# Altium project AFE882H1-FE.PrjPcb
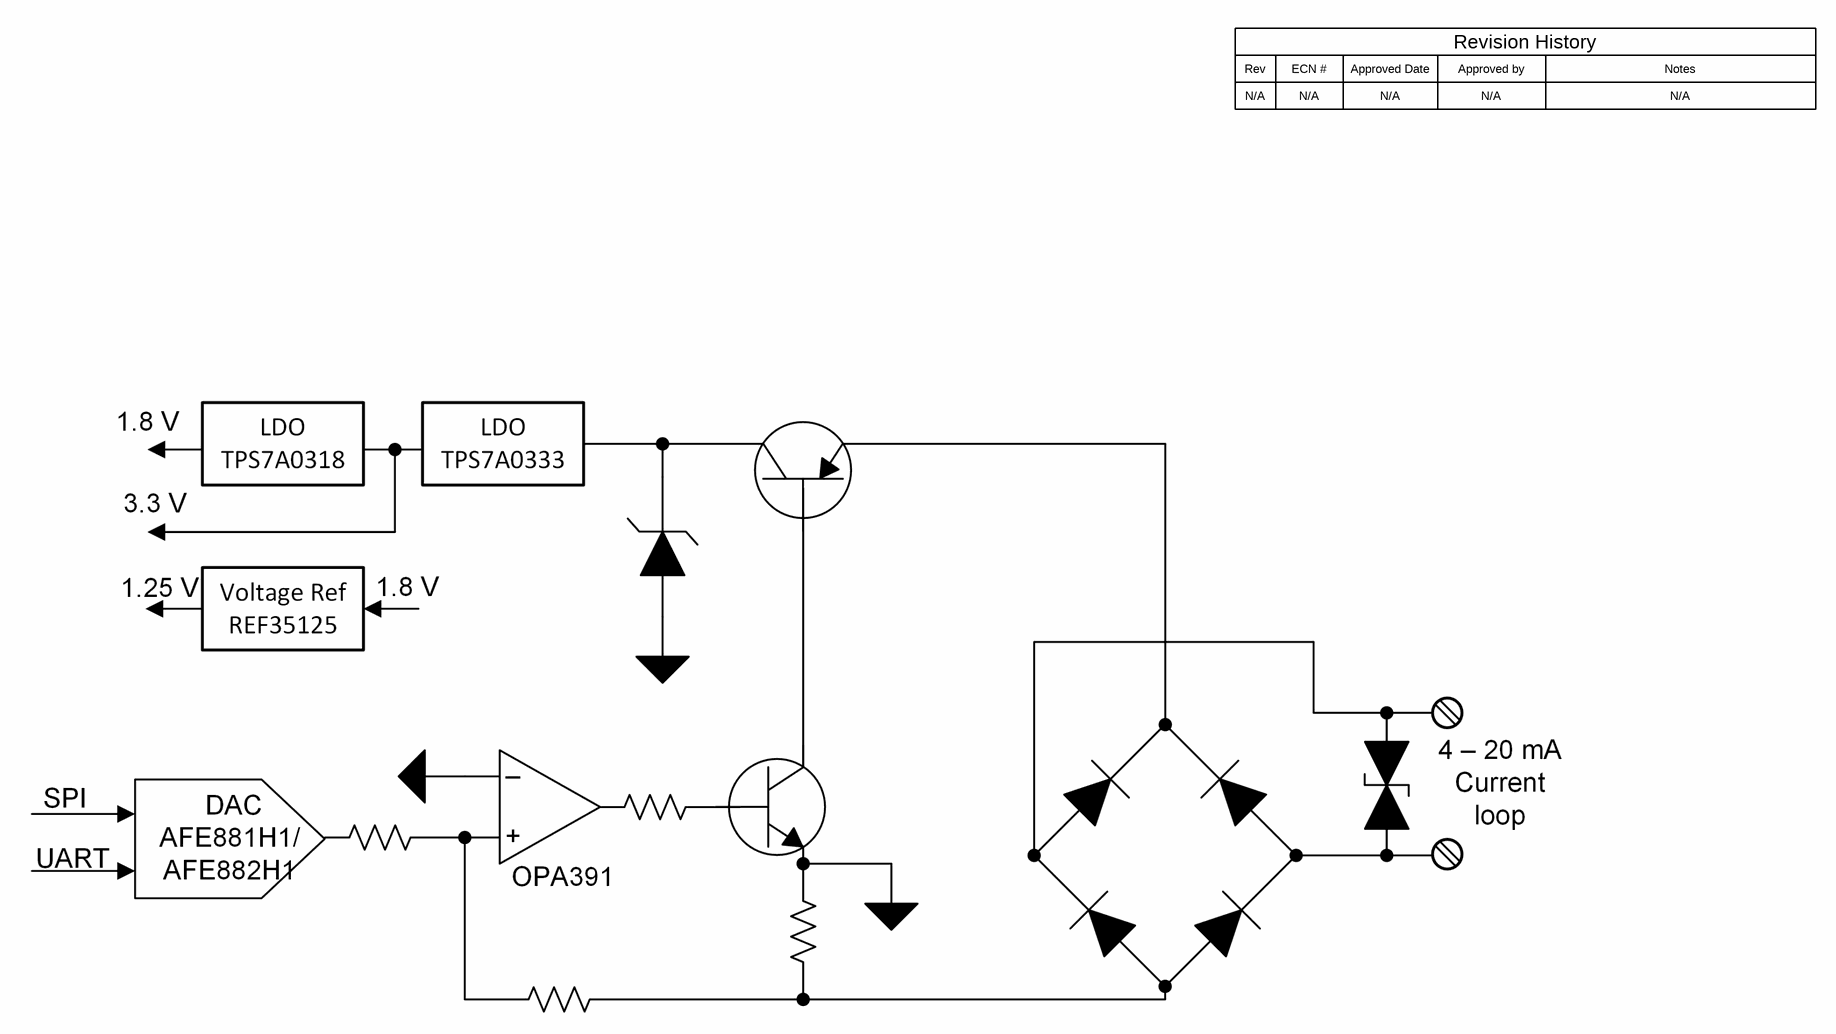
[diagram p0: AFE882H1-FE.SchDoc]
TID: N/A; TechSupport: http://www.ti.com/support; SCH_Rev: E3; PRJ_Title: FT-EVP-AFE; PRJ_Number: TIDA-010982; PRJ_Engineer: A. Noeman; PRJ_Customer: Public Release; PCB_Rev: E3; PCB_Layout: A. Noeman; CopyrightYear: 2024
3 sheets, 102 parts. Net scope: global (net labels, ports and power ports of the same name join across sheets).
Board file: AFE882H1-FE_SG.PcbDoc
Sheets:
  AFE882H1-FE.SchDoc
  AFE882H1-FE_AFE.SchDoc
  AFE882H1-FE_Hardware.SchDoc

## Sheet AFE882H1-FE.SchDoc
size 431 x 279 mm; Date: Not shown in title block; ApprovedBy: Not shown in title block; CheckedBy: Not shown in title block; Author: Not shown in title block; CompanyName: Not shown in title block; Engineer: Not shown in title block; Organization: Not shown in title block; Address1: Not shown in title block; Address2: Not shown in title block; Address3: Not shown in title block; Address4: Not shown in title block; DocumentNumber: 1; Revision: Use project parameter SCH_Rev; SheetNumber: 1; SheetTotal: 3; PageSetup: Record=PageOptions¦CenterHorizontal=True¦CenterVertical=True¦PrintScale=1.00¦XCorrection=1.00¦YCorrection=1.00¦PrintKind=0¦BorderSize=5000000¦LeftOffset=0¦BottomOffset=0¦Orientation=2¦PaperLength=1000¦PaperWidth=1000¦Scale=100¦PaperSource=15¦PrintQuality=600¦MediaType=1¦DitherType=10¦PaperKind=Letter¦PrintScaleMode=1

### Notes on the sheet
- Rev
- N/A
- ECN #
- Approved Date
- Approved by
- Revision History
- Notes

## Sheet AFE882H1-FE_AFE.SchDoc
size 431 x 279 mm; Date: Not shown in title block; ApprovedBy: Not shown in title block; CheckedBy: Not shown in title block; Author: Not shown in title block; CompanyName: Not shown in title block; Engineer: Not shown in title block; Organization: Not shown in title block; Address1: Not shown in title block; Address2: Not shown in title block; Address3: Not shown in title block; Address4: Not shown in title block; DocumentNumber: 2; Revision: Use project parameter SCH_Rev; SheetNumber: 2; SheetTotal: 3; PageSetup: Record=PageOptions¦CenterHorizontal=True¦CenterVertical=True¦PrintScale=1.00¦XCorrection=1.00¦YCorrection=1.00¦PrintKind=0¦BorderSize=5000000¦LeftOffset=0¦BottomOffset=0¦Orientation=2¦PaperLength=1000¦PaperWidth=1000¦Scale=100¦PaperSource=15¦PrintQuality=600¦MediaType=1¦DitherType=10¦PaperKind=Letter¦PrintScaleMode=1
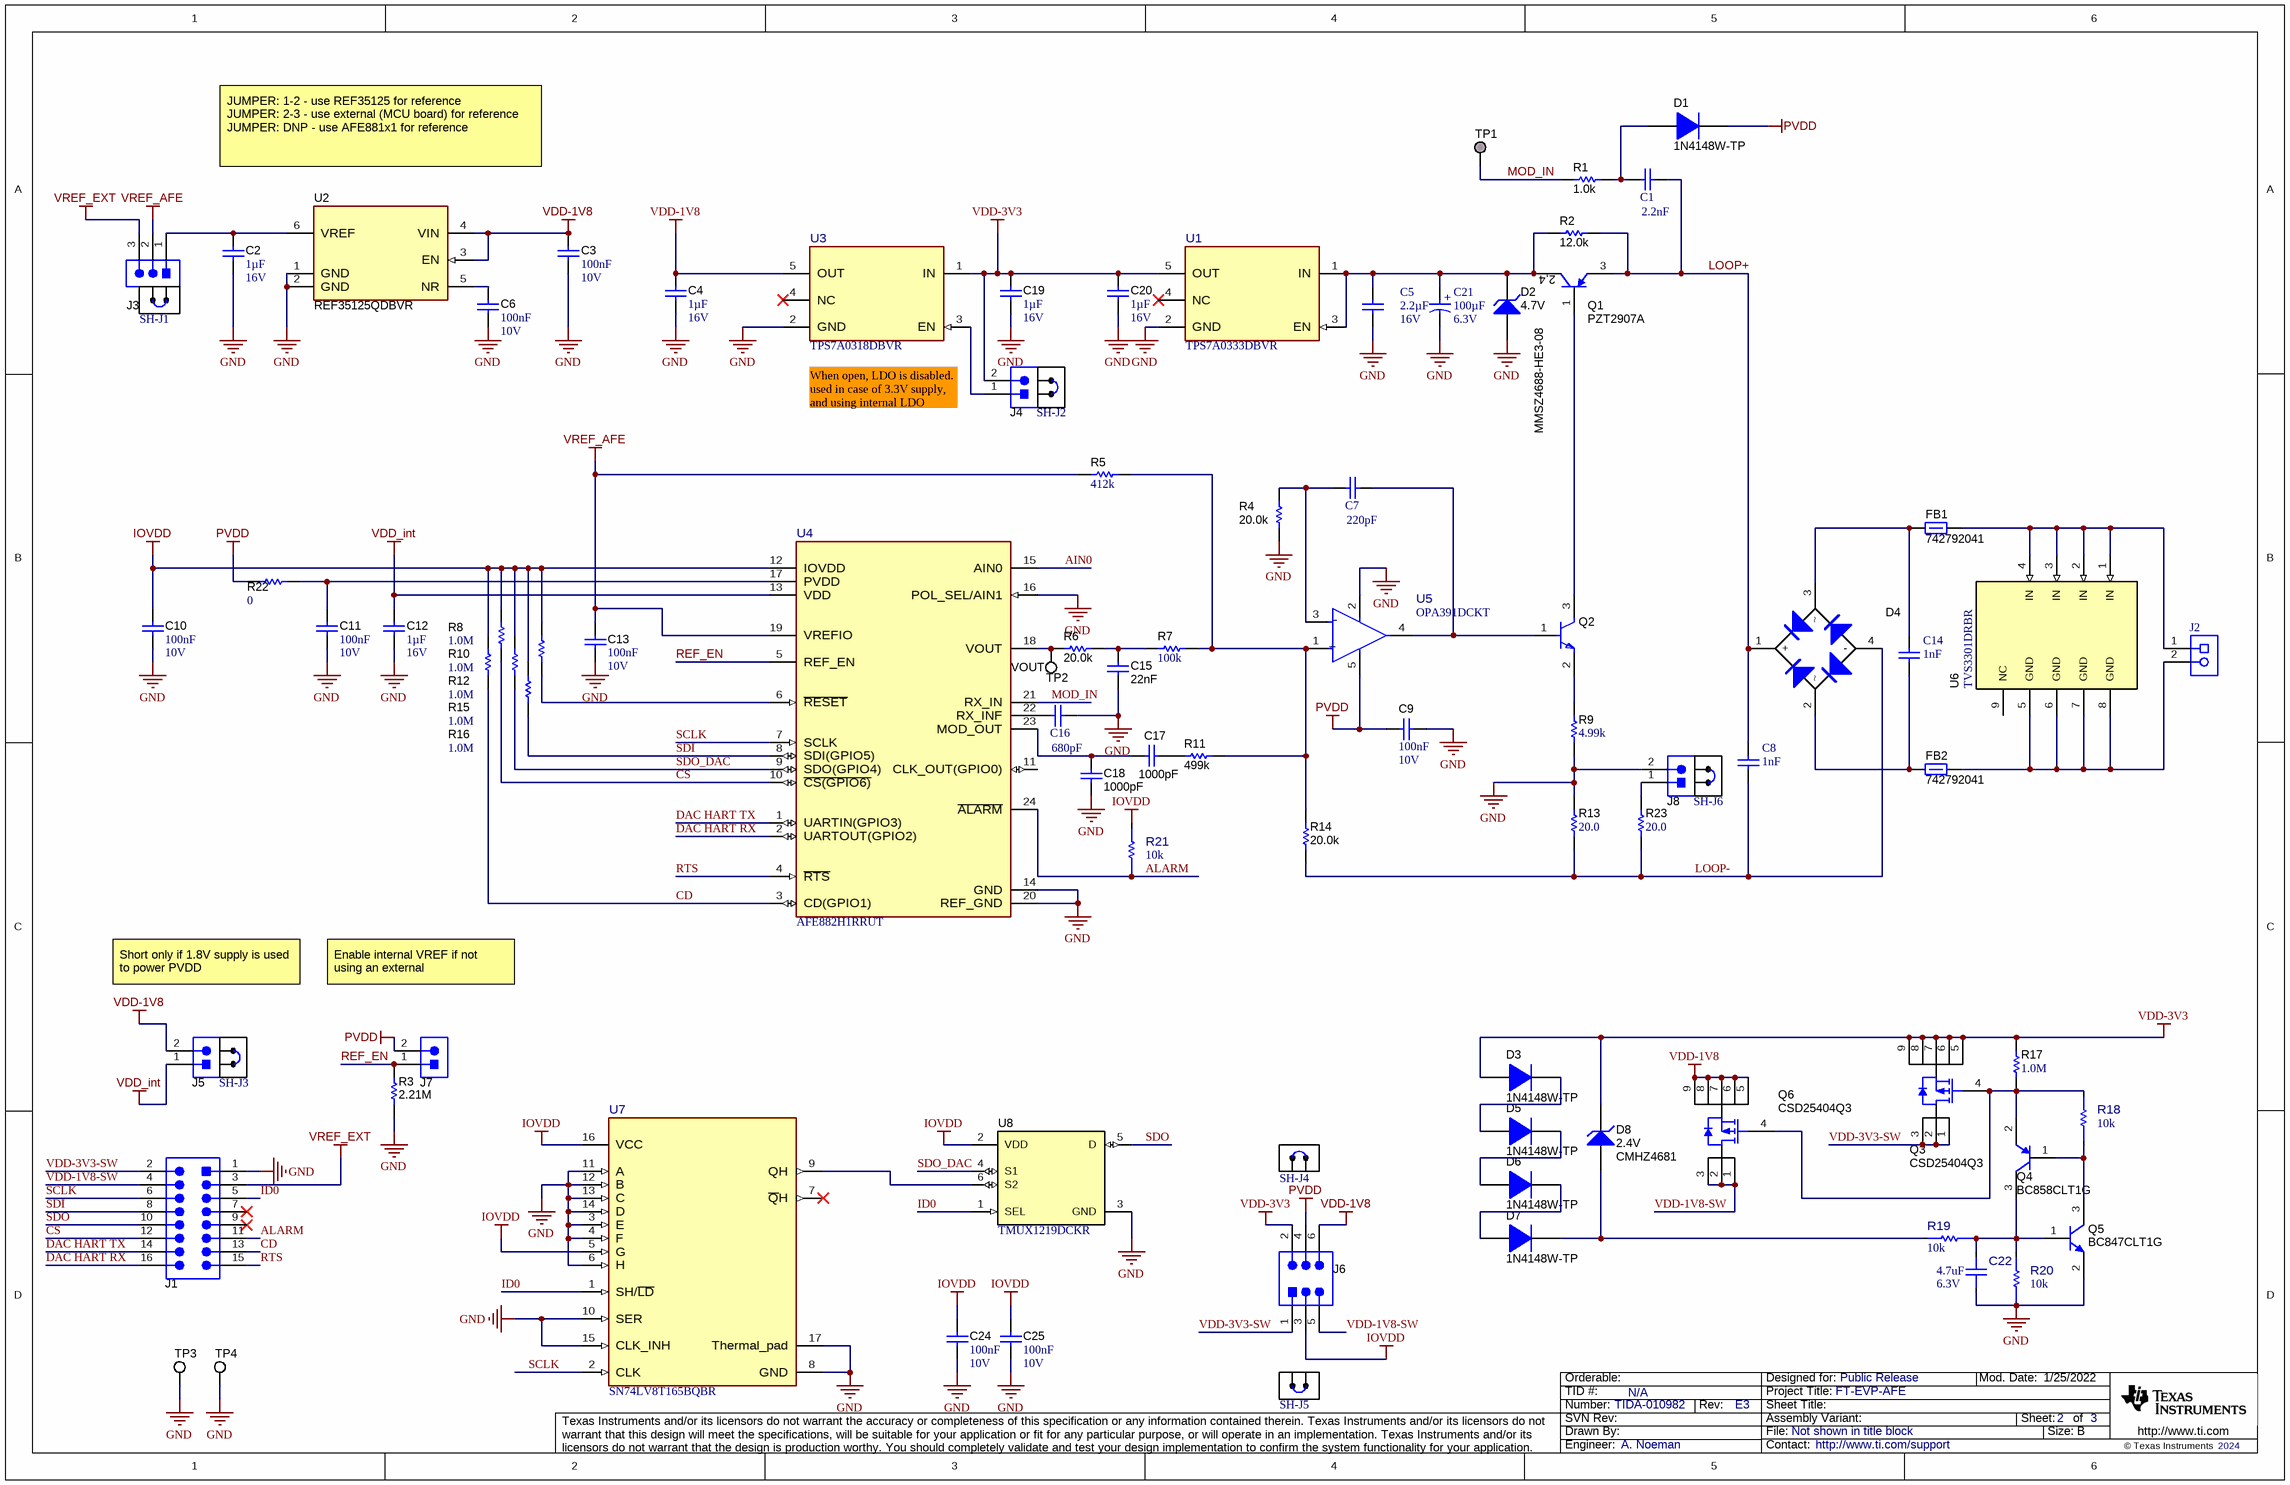
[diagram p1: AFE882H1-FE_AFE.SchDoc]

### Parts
C1  Cap_F: 2.2nF  [WCAP-CSGP_0603_L1.6W0.8H0.8_Reflow]  (hidden comment: 885012006015)
C2  Cap_F: 1µF  VDC_V: 16V  [0603]  (hidden comment: 885012206052)
C3  Cap_F: 100nF  VDC_V: 10V  [0603]  (hidden comment: 885012206020)
C4  Cap_F: 1µF  VDC_V: 16V  [0603]  (hidden comment: 885012206052)
C5  Cap_F: 2.2µF  Rated Voltage (DC): 16V  [WCAP-CSGP_0805_L2W1.25H1.25]  (hidden comment: 885012207052)
C6  Cap_F: 100nF  VDC_V: 10V  [0603]  (hidden comment: 885012206020)
C7  Cap_F: 220pF  [WCAP-CSGP_0603_L1.6W0.8H0.8_Reflow]  (hidden comment: 885012006010)
C8  Cap_F: 1nF  [WCAP-CSGP_0805_L2W1.25H0.8_Reflow]  (hidden comment: 885012207086)
C9  Cap_F: 100nF  VDC_V: 10V  [0603]  (hidden comment: 885012206020)
C10  Cap_F: 100nF  VDC_V: 10V  [0603]  (hidden comment: 885012206020)
C11  Cap_F: 100nF  VDC_V: 10V  [0603]  (hidden comment: 885012206020)
C12  Cap_F: 1µF  VDC_V: 16V  [0603]  (hidden comment: 885012206052)
C13  Cap_F: 100nF  VDC_V: 10V  [0603]  (hidden comment: 885012206020)
C14  Cap_F: 1nF  [WCAP-CSGP_0805_L2W1.25H0.8_Reflow]  (hidden comment: 885012207086)
C15  Cap_F: 22nF  [0603]  (hidden comment: 885012206091)
C16  Cap_F: 680pF  [WCAP-CSGP_0603_L1.6W0.8H0.8_Reflow]  (hidden comment: 885012006013)
C17  ValueDisplayed: 1000pF  [0402]  (hidden comment: 885012205061)
C18  ValueDisplayed: 1000pF  [0402]  (hidden comment: 885012205061)
C19  Cap_F: 1µF  VDC_V: 16V  [0603]  (hidden comment: 885012206052)
C20  Cap_F: 1µF  VDC_V: 16V  [0603]  (hidden comment: 885012206052)
C21  Cap_F: 100µF  Rated Voltage (DC): 6.3V  [WCAP-AS5H_D6.3H5.5]  (hidden comment: 865230143004)
C22  ValueDisplayed: 4.7uF  VDC_V: 6.3V  [FP-885012106005_0603-MFG]  (hidden comment: 885012106005)
C24  Cap_F: 100nF  VDC_V: 10V  [0603]  (hidden comment: 885012206020)
C25  Cap_F: 100nF  VDC_V: 10V  [0603]  (hidden comment: 885012206020)
D1  1N4148W-TP  [SOD-123]
D2  MMSZ4688-HE3-08  value 4.7V  [SOD-123]
D3  1N4148W-TP  [SOD-123]
D4  CD-MBL206SL  [CD-MBL2xxS]  (value not drawn)
D5  1N4148W-TP  [SOD-123]
D6  1N4148W-TP  [SOD-123]
D7  1N4148W-TP  [SOD-123]
D8  CMHZ4681  value 2.4V  [SOD-123]
FB1  742792041  [0805_HV]
FB2  742792041  [0805_HV]
J1  61301621021  [Wurth_61301621021]  (value not drawn)
J2  691214310002  [Wurth_691214310002]  (value not drawn)
J3  61300311121  [WURTH_61300311121]  (value not drawn)
J4  61300211121  [WURTH_61300211121]  (value not drawn)
J5  61300211121  [WURTH_61300211121]  (value not drawn)
J6  61300621121  [Wurth_61300621121]  (value not drawn)
J7  61300211121  [WURTH_61300211121]  (value not drawn)
J8  61300211121  [WURTH_61300211121]  (value not drawn)
Q1  PZT2907A  [SOT-223]
Q2  SMMBT3904LT3G  [FP-SMMBT3904LT3G_SOT23-MFG]  (value not drawn)
Q3  CSD25404Q3  [DQG0008A]
Q4  BC858CLT1G  [SOT-23]
Q5  BC847CLT1G  [SOT-23]
Q6  CSD25404Q3  [DQG0008A]
R1  ValueDisplayed: 1.0k  [0603]  (hidden comment: RC0603JR-071KL)
R2  ValueDisplayed: 12.0k  [0805_HV]  (hidden comment: RG2012P-123-B-T5)
R3  ValueDisplayed: 2.21M  [0603]  (hidden comment: RC0603FR-072M21L)
R4  ValueDisplayed: 20.0k  [0603]  (hidden comment: RG1608P-203-B-T5)
R5  ValueDisplayed: 412k  [0603]  (hidden comment: RT0603BRD07412KL)
R6  ValueDisplayed: 20.0k  [0603]  (hidden comment: RG1608P-203-B-T5)
R7  ValueDisplayed: 100k  [0603]  (hidden comment: RG1608P-104-B-T5)
R8  ValueDisplayed: 1.0M  [0603]  (hidden comment: CRCW06031M00JNEA)
R9  ValueDisplayed: 4.99k  [0603]  (hidden comment: RT0603BRD074K99L)
R10  ValueDisplayed: 1.0M  [0603]  (hidden comment: CRCW06031M00JNEA)
R11  ValueDisplayed: 499k  [0603]  (hidden comment: RT0603DRE07499KL)
R12  ValueDisplayed: 1.0M  [0603]  (hidden comment: CRCW06031M00JNEA)
R13  ValueDisplayed: 20.0  [0805_HV]  (hidden comment: RT0805BRD0720RL)
R14  ValueDisplayed: 20.0k  [0603]  (hidden comment: RG1608P-203-B-T5)
R15  ValueDisplayed: 1.0M  [0603]  (hidden comment: CRCW06031M00JNEA)
R16  ValueDisplayed: 1.0M  [0603]  (hidden comment: CRCW06031M00JNEA)
R17  ValueDisplayed: 1.0M  [0603]  (hidden comment: CRCW06031M00JNEA)
R18  value 10k  [FP-CRCW060310K0FKEAC_0603-MFG]  (hidden comment: CRCW060310K0FKEAC)
R19  value 10k  [FP-CRCW060310K0FKEAC_0603-MFG]  (hidden comment: CRCW060310K0FKEAC)
R20  value 10k  [FP-CRCW060310K0FKEAC_0603-MFG]  (hidden comment: CRCW060310K0FKEAC)
R21  value 10k  [FP-CRCW060310K0FKEAC_0603-MFG]  (hidden comment: CRCW060310K0FKEAC)
R22  ValueDisplayed: 0  [0603]  (hidden comment: RCS06030000Z0EA)
R23  ValueDisplayed: 20.0  [0805_HV]  (hidden comment: RT0805BRD0720RL)
SH-J1  60900213421  [Wurth_60900213421]  (value not drawn)
SH-J2  60900213421  [Wurth_60900213421]  (value not drawn)
SH-J3  60900213421  [Wurth_60900213421]  (value not drawn)
SH-J4  60900213421  [Wurth_60900213421]  (value not drawn)
SH-J5  60900213421  [Wurth_60900213421]  (value not drawn)
SH-J6  60900213421  [Wurth_60900213421]  (value not drawn)
TP1  TP_H0.45P0.75  [TP_H045P075]  (value not drawn)  (no BOM)
TP2  VOUT  [Keystone5002]
TP3  GND  [Keystone5002]  (value not drawn)
TP4  GND  [Keystone5002]  (value not drawn)
U1  TPS7A0333DBVR  [DBV0005A-MFG]
U2  REF35125QDBVR  [DBV0006A-MFG]
U3  TPS7A0318DBVR  [DBV0005A-MFG]
U4  AFE882H1RRUT  [RRU0024A-MFG]
U5  OPA391DCKT  [DCK0005A-MFG]
U6  TVS3301DRBR  [DRB0008A]
U7  SN74LV8T165BQBR  [BQB0016A-MFG]
U8  TMUX1219DCKR  [DCK0006A_N]  (no BOM)

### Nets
GND: C2.2 C3.2 C4.2 C5.1 C6.2 C9.2 C10.2 C11.2 C12.2 C13.2 C15.2 C16.2 C18.1 C19.2 C20.2 C21.2(N) C22.1 C24.2 C25.2 D2.2(A) J1.1 J8.2 Q5.2(E) R3.2 R4.1 R9.1 R13.2 R20.1 TP3.1 TP4.1 U1.2(GND) U2.1(GND) U2.2(GND) U3.2(GND) U4.14(GND) U4.16(POL_SEL/AIN1) U4.20(REF_GND) U5.2(V-) U7.3(E) U7.4(F) U7.6(H) U7.8(GND) U7.10(SER) U7.11(A) U7.12(B) U7.13(C) U7.14(D) U7.15(CLK_INH) U7.17(Thermal_pad) U8.3(GND)
IOVDD: C10.1 C24.1 C25.1 J6.3 R8.2 R10.2 R12.2 R15.2 R16.2 R21.2 U4.12(IOVDD) U7.5(G) U7.16(VCC) U8.2(VDD)
PVDD: C9.1 D1.1(K) J6.4 J7.2 R22.1 U5.5(V+)
VDD-1V8: C3.1 C4.1 J5.2 J6.6 Q6.5(S) Q6.6(S) Q6.7(S) Q6.8(S) Q6.9(S) U2.3(EN) U2.4(VIN) U3.5(OUT)
VDD-3V3: C19.1 C20.1 D3.2(A) D8.1(K) J4.2 J6.2 Q3.5(S) Q3.6(S) Q3.7(S) Q3.8(S) Q3.9(S) R17.2 U1.5(OUT) U3.1(IN)
VDD_int: C12.1 J5.1 U4.13(VDD)
VREF_AFE: C13.1 J3.2 R5.1 U4.19(VREFIO)
VREF_EXT: J1.3 J3.3
AIN0: U4.15(AIN0)
ALARM: J1.11 R21.1 U4.24(~{ALARM})
CD: J1.13 R16.1 U4.3(CD(GPIO1))
CS: J1.12 R15.1 U4.10(~{CS(GPIO6)})
DAC HART RX: J1.16 U4.2(UARTOUT(GPIO2))
DAC HART TX: J1.14 U4.1(UARTIN(GPIO3))
ID0: J1.5 U7.1(SH/~{LD}) U8.1(SEL)
LOOP+: C1.2 C8.2 D4.1(+) Q1.3(E) R2.2
LOOP-: C8.1 D4.4(-) R13.1 R14.1 R23.1
MOD_IN: R1.1 TP1.1 U4.21(RX_IN)
REF_EN: J7.1 R3.1 U4.5(REF_EN)
RTS: J1.15 U4.4(~{RTS})
SCLK: J1.6 U4.7(SCLK) U7.2(CLK)
SDI: J1.8 R10.1 U4.8(SDI(GPIO5))
SDO: J1.10 U8.5(D)
SDO_DAC: R12.1 U4.9(SDO(GPIO4)) U8.4(S1)
VDD-1V8-SW: J1.4 J6.5 Q6.1(D) Q6.2(D) Q6.3(D)
VDD-3V3-SW: J1.2 J6.1 Q3.1(D) Q3.2(D) Q3.3(D)
NetC1_1: C1.1 D1.2(A) R1.2
NetC2_1: C2.1 J3.1 U2.6(VREF)
NetC5_2: C5.2 C21.1(P) D2.1(K) Q1.2(C) Q1.4(C) R2.1 U1.1(IN) U1.3(EN)
NetC6_1: C6.1 U2.5(NR)
NetC7_1: C7.1 R4.2 U5.3(-IN)
NetC7_2: C7.2 Q2.1(BASE) U5.4(OUT)
NetC11_1: C11.1 R22.2 U4.17(PVDD)
NetC14_1: C14.1 D4.2 FB2.1
NetC14_2: C14.2 D4.3 FB1.1
NetC15_1: C15.1 R6.1 R7.1
NetC16_1: C16.1 U4.22(RX_INF)
NetC17_1: C17.1 R11.1
NetC17_2: C17.2 C18.2 U4.23(MOD_OUT)
NetC22_2: C22.2 Q4.3(C) Q5.1(B) R19.1 R20.2
NetD3_1: D3.1(K) D5.2(A)
NetD5_1: D5.1(K) D6.2(A)
NetD6_1: D6.1(K) D7.2(A)
NetD7_1: D7.1(K) D8.2(A) R19.2
NetFB1_2: FB1.2 J2.1 U6.1(IN) U6.2(IN) U6.3(IN) U6.4(IN)
NetFB2_2: FB2.2 J2.2 U6.5(GND) U6.6(GND) U6.7(GND) U6.8(GND)
NetJ4_1: J4.1 U3.3(EN)
NetJ8_1: J8.1 R23.2
NetQ1_1: Q1.1(B) Q2.3(COLLECTOR)
NetQ2_2: Q2.2(EMITTER) R9.2
NetQ3_4: Q3.4(G) Q4.2(E) Q6.4(G) R17.1 R18.2
NetQ4_1: Q4.1(B) Q5.3(C) R18.1
NetR5_2: R5.2 R7.2 R11.2 R14.2 U5.1(+IN)
NetR6_2: R6.2 TP2.1 U4.18(VOUT)
NetR8_1: R8.1 U4.6(~{RESET})
NetU7_9: U7.9(QH) U8.6(S2)

Not connected (* = marked no-connect by the designer): J1 7* 9*; U1 4(NC)*; U3 4(NC)*; U4 11(CLK_OUT(GPIO0)); U6 9(NC); U7 7(~{Q}H)*

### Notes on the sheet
- JUMPER: 1-2 - use REF35125 for reference
  JUMPER: 2-3 - use external (MCU board) for reference
  JUMPER: DNP - use AFE881x1 for reference
- When open, LDO is disabled.
  used in case of 3.3V supply, and using internal LDO
- Short only if 1.8V supply is used to power PVDD
- Enable internal VREF if not using an external

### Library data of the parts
C1 = CMP-0107759-1: WCAP-CSGP Multilayer Ceramic Chip Capacitor, General Purpose, size 0603, NP0, 2.2nF, 10VDC; Manufacturer: Wurth Elektronik; Capacitance Tolerance: +/-5%; Case/Size Code: 0603; Insulation Resistance: 10GOhm; Q Factor: 1000; Rated Voltage (DC): 10V; Technical Reference: NP00603222J010DFCT10000
C2 C4 C12 C19 C20 = CMP-0006831-4: CAP, CERM, 1 uF, 16 V, +/- 10%, X7R, 0603; Manufacturer: Wurth Elektronik; TaMin_C: -55°C; Polarized: N; SizeAreaWB_mm2: 4.68; Value1: Unknown; U/M: EA; Value: 1uF; TaMax_C: 125°C; SizeZ_mm: 1; SizeX_mm: 1.6; SizeY_mm: 0.8; SizeArea_mm2: 1.28; AEC Category: Q200
C3 C6 C9-C11 C13 C24 C25 = CMP-0064931-4: CAP, CERM, 0.1 uF, 10 V,+/- 10%, X7R, 0603; Manufacturer: Wurth Elektronik; TaMin_C: -55°C; Polarized: N; SizeAreaWB_mm2: 4.68; Value1: Unknown; U/M: EA; Value: 0.1uF; TaMax_C: 125°C; SizeZ_mm: 1; SizeX_mm: 1.6; SizeY_mm: 0.8; SizeArea_mm2: 1.28; AEC Category: Q200
C5 = CMP-0115546-1: WCAP-CSGP Multilayer Ceramic Chip Capacitor, General Purpose, size 0805, X7R, 2.2µF, 16VDC; Manufacturer: Wurth Elektronik; Capacitance Tolerance: +/-10%; Case/Size Code: 0805; Dissipation Factor: 10%; Insulation Resistance: 0.05GOhm; Technical Reference: X7R0805225K016DFCT10000
C7 = CMP-0114923-1: WCAP-CSGP Multilayer Ceramic Chip Capacitor, General Purpose, size 0603, NP0, 220pF, 10VDC; Manufacturer: Wurth Elektronik; Capacitance Tolerance: +/-5%; Case/Size Code: 0603; Insulation Resistance: 10GOhm; Q Factor: 1000; Rated Voltage (DC): 10V; Technical Reference: NP00603221J010DFCT10000
C8 C14 = CMP-0104837-1: WCAP-CSGP Multilayer Ceramic Chip Capacitor, General Purpose, size 0805, X7R, 1nF, 50VDC; Manufacturer: Wurth Elektronik; Capacitance Tolerance: +/-10%; Case/Size Code: 0805; Dissipation Factor: 2.5%; Insulation Resistance: 10GOhm; Rated Voltage (DC): 50V; Technical Reference: X7R0805102K050DFCT10000
C15 = CMP-0006836-4: CAP, CERM, 0.022 uF, 50 V, +/- 10%, X7R, 0603; Manufacturer: Wurth Elektronik; TaMin_C: -55°C; Polarized: N; SizeAreaWB_mm2: 4.68; Value1: Unknown; U/M: EA; TaMax_C: 125°C; SizeZ_mm: 1; SizeX_mm: 1.6; SizeY_mm: 0.8; Value2: 50V; SizeArea_mm2: 1.28; AEC Category: Q200
C16 = CMP-0104183-1: WCAP-CSGP Multilayer Ceramic Chip Capacitor, General Purpose, size 0603, NP0, 680pF, 10VDC; Manufacturer: Wurth Elektronik; Capacitance Tolerance: +/-5%; Case/Size Code: 0603; Insulation Resistance: 10GOhm; Q Factor: 1000; Rated Voltage (DC): 10V; Technical Reference: NP00603681J010DFCT10000
C17 C18 = CMP-0006231-2: CAP, CERM, 1000 pF, 50 V, +/- 10%, X7R, 0402; Manufacturer: Wurth Elektronik; TaMin_C: -55°C; Polarized: N; SizeAreaWB_mm2: 3; Value1: Unknown; U/M: EA; Value: 1000pF; TaMax_C: 125°C; SizeZ_mm: 0.6; SizeX_mm: 1; SizeY_mm: 0.5; Value2: 50V; Cap_F: 1nF; AEC Category: Q200
C21 = CMP-0107158-1: WCAP-AS5H Aluminum Electrolytic Capacitor, V-Chip, D6.3 x H5.5mm, 100µF, 6.3V; Manufacturer: Wurth Elektronik; Capacitance Tolerance: +/-20%; Dissipation Factor: 32%; Endurance: 5000h; Leakage Current: 6.3uA; Ripple Current: 60mA; Technical Reference: ASDD055101M6R3DVCTBE000
C22 = CMP-0049191-1: 4.7 µF ±20% 6.3V Ceramic Capacitor X5R 0603 (1608 Metric); Manufacturer: Wurth Electronics; AEC Qualified: No; Cap_F: 4.7µF; SizeZ_mm: 1mm; TempCo: 15%; Value: 4.7µF
D1 D3 D5-D7 = CMP-0076974-2: Diode, Switching, 100 V, 0.15 A, SOD-123; Manufacturer: Micro Commercial Components; Io_A: 150mA; SizeX_mm: 3.85; SizeY_mm: 1.7; Green_REACh: Incomplete; AEC Category: Q101; TJmax_C: 150°C; Value1: 0.15A; Vf_V: 1.25V; Value: 100V; SizeZ_mm: 1.35; SizeArea_mm2: 6.545; SizeAreaWB_mm2: 13.095; Green_Lifecycle: Not Set
D2 = CMP-0077561-3: Diode, Zener, 4.7 V, 500 mW, AEC-Q101, SOD-123; Manufacturer: Vishay-Semiconductor; SizeY_mm: 1.7; SizeX_mm: 3.85; SizeArea_mm2: 6.545; RJA_CperW: 340; SizeZ_mm: 1.35; AEC Qualified: Y; Power_W: 500mW; Value1: 0.5W; AEC Category: Q101; SizeAreaWB_mm2: 13.095
D4 = CMP-0067544-2: Diode, P-N-Bridge, 600 V, 2 A, 5.8x5.3mm; Manufacturer: Bourns; SizeAreaWB_mm2: 47.092; SizeX_mm: 5.72; AEC Qualified: N; Io_A: 2A; Vf_V: 960mV; Value2: 0.96V; SizeZ_mm: 1.35; SizeArea_mm2: 23.452; AEC Category: Q101; RJC_CperW: 15.0; Value: 600V; TJmax_C: 175°C; SizeY_mm: 4.1
D8 = CMP-0085120-1: Diode, Zener, 3 V, 500 mW, AEC-Q101, SOD-123; Value1: 0.5W; SizeZ_mm: 1.35; AEC Category: Q101; Vz_V: 2.4 V; SizeY_mm: 1.7; SizeArea_mm2: 6.545; SizeAreaWB_mm2: 13.095; Power_W: 500mW; AEC Qualified: Y; RJA_CperW: 425; SizeX_mm: 3.85
FB1 FB2 = CMP-0003085-1: Ferrite Bead, 600 ohm @ 100 MHz, 0.2 A, 0805; Manufacturer: Wurth Elektronik; Ztyp@1GHz_Ohm: 200.287; ZTyp@100MHz_Ohm: 600; SizeAreaWB_mm2: 6.75; DCR_ohm: 0.4; Value1: 0.4 ohm; Value: 600 ohm; Imax_A: 200mA; SizeZ_mm: 1.45; SizeX_mm: 2; SizeY_mm: 1.25; Value2: 0.2A; SizeArea_mm2: 2.5
J1 = CMP-0081505-1: Header, 2.54mm, 8x2, Gold, R/A, TH; Manufacturer: Wurth Elektronik; Pitch_mm: 2.54; Gender: Male; Cert_UL: Y; Current_A: 3A; Voltage_V: 250V; Shrouded: N; Row_Count: 2
J2 = CMP-0054822-2: Terminal Block, 2x1, 3.81mm, 24-16 AWG, 10A, 300VAC, TH; Manufacturer: Wurth Elektronik; CT: TRUE; CNHeader: FALSE; Green_Lifecycle: Active; Green_REACh: Passed
J3 = CMP-0054796-4: Header, 2.54 mm, 3x1, Gold, TH; Manufacturer: Wurth Elektronik; Green_REACh: Passed; CT: FALSE; CNHeader: TRUE; Green_Lifecycle: Active
J4 J5 J7 J8 = CMP-0054794-2: Header, 2.54 mm, 2x1, Gold, TH; Manufacturer: Wurth Elektronik; Shrouded: N; Gender: Male; Green_REACh: Passed; Pitch_mm: 2.54; Green_Lifecycle: Active; Row_Count: 1; Cert_UL: Y
J6 = CMP-0054802-2: Header, 2.54mm, 3x2, Gold, TH; Manufacturer: Wurth Elektronik; Green_Lifecycle: Active; Shrouded: N; Gender: Male; Green_REACh: Passed; Row_Count: 2; RowSpacing_mm: 2.54
Q1 = CMP-0000355-2: Transistor, PNP, 60 V, 0.8 A, SOT-223; Manufacturer: Fairchild Semiconductor; TaMax_C: 150°C; Value2: 300; Value1: 0.8 A; Vcesat1_V: 4dV; SizeX_mm: 6.5; SizeY_mm: 7; TaMin_C: -55°C; IcRated_A: 8dA; CompType: BJT; SizeZ_mm: 1.6; AEC Qualified: N; Value: 60 V; SizeArea_mm2: 45.5; NPN: 0; Vceo_V: 60V; PNP: 1; AEC Category: Q101; SizeAreaWB_mm2: 76.5; U/M: EA
Q2 = CMP-0097440-1: Bipolar (BJT) Transistor NPN 40 V 200 mA 300MHz 300 mW Surface Mount SOT-23-3 (TO-236); Manufacturer: On Semiconductor; Collector Base Voltage: 60V; Hfe Testvce: 1V; Hfe Max: 300; Power_W: 225mW; Hfe Ss Min: 100; Hfe Testic: 10mA; Import Ts: 1521847306; Vceo_V: 40V; Hfe Ss Testvce: 10V; Ciiva Ids: 19584013; Emitter Base Voltage: 6V; Number Of Npn: 1; Rthja Max: 556°C/W; AEC Grade: Grade 0; Hfe Ss Testic: 1mA; TJmax_C: +150°C; Value: 40V; Vcesat1_V: 300mV; SizeZ_mm: 1.11mm; IcRated_A: 200mA; Hfe Ss Max: 400; Standoff Height: 0.01mm; Rise Time Tr: 35ns; Fall Time Tf: 50ns; AEC Qualified: Yes
Q3 Q6 = CMP-0000026-3: MOSFET, P-CH, -20 V, -60 A, DQG0008A (VSON-CLIP-8); Manufacturer: Texas Instruments; Alternate Manufacturer: None; ChMode: Enhancement; SizeY_mm: 3.3; AEC Category: Q101; VdsMax_V: -20V; Value2: 10.8 nC; SizeZ_mm: 1.1; Value: -20V; SizeAreaWB_mm2: 18.49; AEC Qualified: N; IdsMax_A: -60A; SizeArea_mm2: 10.89; Vgs_V: -12V; QgTyp_nC: 10.8; Rdson45_ohm: 6.5m; Value1: 0.006; ChType: P
Q4 = CMP-0000342-2: Transistor, PNP, 30 V, 0.1 A, SOT-23; Manufacturer: ON Semiconductor; TaMax_C: 150°C; Value2: 800; Value1: 0.1 A; Vcesat1_V: 650mV; SizeX_mm: 2.5; SizeY_mm: 3; TaMin_C: -55°C; IcRated_A: 100mA; CompType: BJT; SizeZ_mm: 1.1; Value: 30 V; SizeArea_mm2: 7.5; NPN: 0; Vceo_V: 30V; PNP: 1; AEC Category: Q101; SizeAreaWB_mm2: 14; U/M: EA
Q5 = CMP-0000376-2: Transistor, NPN, 45 V, 0.1 A, SOT-23; Manufacturer: ON Semiconductor; TaMax_C: 150°C; Value2: 800; Value1: 0.1 A; Vcesat1_V: 700mV; SizeX_mm: 2.5; SizeY_mm: 3; TaMin_C: -55°C; IcRated_A: 100mA; CompType: BJT; SizeZ_mm: 1.1; Value: 45 V; SizeArea_mm2: 7.5; NPN: 1; Vceo_V: 45V; PNP: 0; AEC Category: Q101; SizeAreaWB_mm2: 14; U/M: EA
R1 = CMP-0025899-5: RES, 1.0 k, 5%, 0.1 W, 0603; Manufacturer: Yageo; Power_W: 100mW; TempCo: 100 ppm/C; Value_Code: 1k00; Value: 1.0k; EIA_Code: E24; Res_ohm: 1k; SizeX_mm: 1.6; SizeY_mm: 0.8; SizeZ_mm: 1; Value2: 0.1W; SizeArea_mm2: 1.28; AEC Qualified: N; VDC_V: 75V; AEC Category: Q200; SizeAreaWB_mm2: 4.68
R2 = CMP-0018871-2: RES, 12.0 k, 0.1%, 0.125 W, 0805; Manufacturer: Susumu Co Ltd; Power_W: 125mW; TempCo: 25 ppm/C; Value_Code: 12k0; U/M: EA; Value: 12.0k; EIA_Code: E192; Res_ohm: 12k; SizeX_mm: 2; SizeY_mm: 1.25; SizeZ_mm: 1.45; Value2: 0.125W; SizeArea_mm2: 2.5; VDC_V: 100V; AEC Category: Q200
R3 = CMP-0023001-4: RES, 2.21 M, 1%, 0.1 W, 0603; Manufacturer: Yageo; Power_W: 100mW; TempCo: 100 ppm/C; Value_Code: 2M21; Value: 2.21Meg; EIA_Code: E96; SizeX_mm: 1.6; SizeY_mm: 0.8; SizeZ_mm: 1; Value2: 0.1W; SizeArea_mm2: 1.28; AEC Qualified: N; VDC_V: 75V; AEC Category: Q200; SizeAreaWB_mm2: 4.68
R4 R6 R14 = CMP-0023464-3: RES, 20.0 k, 0.1%, 0.1 W, 0603; Manufacturer: Susumu Co Ltd; Power_W: 100mW; TempCo: 25 ppm/C; Value_Code: 20k0; U/M: EA; Value: 20.0k; EIA_Code: E192; Res_ohm: 20k; SizeX_mm: 1.6; SizeY_mm: 0.8; SizeZ_mm: 1; Value2: 0.1W; SizeArea_mm2: 1.28; VDC_V: 75V; AEC Category: Q200
R5 = CMP-0024218-3: RES, 412 k, 0.1%, 0.1 W, 0603; Manufacturer: Yageo America; Power_W: 100mW; TempCo: 25 ppm/C; U/M: EA; Value: 412k; EIA_Code: E192; SizeX_mm: 1.6; SizeY_mm: 0.8; SizeZ_mm: 1; Value2: 0.1W; SizeArea_mm2: 1.28; VDC_V: 75V; AEC Category: Q200
R7 = CMP-0023405-3: RES, 100 k, 0.1%, 0.1 W, 0603; Manufacturer: Susumu Co Ltd; Power_W: 100mW; TempCo: 25 ppm/C; U/M: EA; Value: 100k; EIA_Code: E192; SizeX_mm: 1.6; SizeY_mm: 0.8; SizeZ_mm: 1; Value2: 0.1W; SizeArea_mm2: 1.28; VDC_V: 75V; AEC Category: Q200
R8 R10 R12 R15-R17 = CMP-0025736-4: RES, 1.0 M, 5%, 0.1 W, AEC-Q200 Grade 0, 0603; Manufacturer: Vishay-Dale; Power_W: 100mW; TempCo: 200 ppm/C; Value_Code: 1M00; Value: 1.0Meg; EIA_Code: E24; Res_ohm: 1M; SizeX_mm: 1.6; SizeY_mm: 0.8; SizeZ_mm: 1; Value2: 0.1W; SizeArea_mm2: 1.28; AEC Qualified: Y; VDC_V: 75V; AEC Category: Q200; AEC Grade: 0
R9 = CMP-0024304-2: RES, 4.99 k, 0.1%, 0.1 W, 0603; Manufacturer: Yageo America; Power_W: 100mW; TempCo: 25 ppm/C; Value_Code: 4k99; U/M: EA; Value: 4.99k; EIA_Code: E192; SizeX_mm: 1.6; SizeY_mm: 0.8; SizeZ_mm: 1; Value2: 0.1W; SizeArea_mm2: 1.28; VDC_V: 75V; AEC Category: Q200
R11 = CMP-0025329-3: RES, 499 k, 0.5%, 0.1 W, 0603; Manufacturer: Yageo America; Power_W: 100mW; TempCo: 50 ppm/C; U/M: EA; Value: 499k; EIA_Code: E192; SizeX_mm: 1.6; SizeY_mm: 0.8; SizeZ_mm: 1; Value2: 0.1W; SizeArea_mm2: 1.28; VDC_V: 75V; AEC Category: Q200
R13 R23 = CMP-0019777-2: RES, 20.0, 0.1%, 0.125 W, 0805; Manufacturer: Yageo America; Power_W: 125mW; TempCo: 25 ppm/C; Value_Code: 20R0; U/M: EA; Value: 20.0; EIA_Code: E192; Res_ohm: 20; SizeX_mm: 2; SizeY_mm: 1.25; SizeZ_mm: 1.45; Value2: 0.125W; SizeArea_mm2: 2.5; VDC_V: 150V; AEC Category: Q200
R18-R21 = CMP-0126304-1: 10 kOhms ±1% 0.1W, 1/10W Chip Resistor 0603 (1608 Metric) Thick Film; Manufacturer: Vishay Semiconductor; AEC Qualified: No; Power_W: 100mW; SizeZ_mm: 0.55mm; TempCo: 100ppm/°C; VDC_V: 75V
R22 = CMP-0081973-1: RES, 0, 0%, 0.25 W, AEC-Q200 Grade 0, 0603; Manufacturer: Vishay-Dale; SizeAreaWB_mm2: 4.68; SizeArea_mm2: 1.28; AEC Qualified: Y; AEC Category: Q200; Value: 0; SizeZ_mm: 1; SizeY_mm: 0.8; Power_W: 250mW; Value2: 0.25W; SizeX_mm: 1.6
SH-J1-SH-J6 = CMP-0003761-2: Shunt, 2.54mm, Gold, Black; Manufacturer: Wurth Elektronik
TP1 = CMP-0003719-1: Testpoint; Manufacturer: Texas Instruments; CompType: Pad
TP2-TP4 = CMP-0055139-2: Test Point, Miniature, White, TH; Manufacturer: Keystone Electronics; ContactFinish: Silver; Green_REACh: Passed; CT: TRUE; Green_Lifecycle: Active; CNHeader: FALSE
U1 = CMP-0123072-1: Nanopower-IQ 200nA 200mA low-dropout (LDO) voltage regulator with fast transient response; Manufacturer: Texas Instruments; SizeZ_mm: 1.45mm; AEC Qualified: No; Accuracy Percentage: 1%; Dropout Voltage: 310mV; Max Supply Voltage: 6V; Min Supply Voltage: 3.8V; Nominal Supply Current: 0.2uA; Number Of Outputs: 1; Output Type: Fixed; Output Voltage: 3.3V; Standoff Height: 0mm; TJmax_C: +125°C
U2 = CMP-0097920-1: Ultra Low-Power, High-Precision Voltage Reference; Manufacturer: Texas Instruments; Output Voltage: 1.25V; TaMin_C: -40°C; SizeZ_mm: 1.45mm; Standoff Height: 0mm; Nominal Supply Current: 0.65uA; AEC Qualified: No; Number Of Outputs: 1; Min Supply Voltage: 1.75V; Reference Type: Series; Max Supply Voltage: 6V; TaMax_C: +125°C; Output Type: Fixed
U3 = CMP-0123071-1: Nanopower-IQ 200nA 200mA low-dropout (LDO) voltage regulator with fast transient response 5-SOT-23 -40 to 125; Manufacturer: Texas Instruments; SizeZ_mm: 1.45mm; AEC Qualified: No; Accuracy Percentage: 1%; Dropout Voltage: 450mV; Max Supply Voltage: 6V; Min Supply Voltage: 2.3V; Nominal Supply Current: 0.2uA; Number Of Outputs: 1; Output Type: Fixed; Output Voltage: 1.8V; Standoff Height: 0mm; TJmax_C: +125°C
U4 = CMP-0096723-1: Manufacturer: Texas Instruments; SizeZ_mm: 0.7mm; Standoff Height: 0mm; AEC Qualified: Unknown
U5 = CMP-0094597-1: General Purpose Amplifier 1 Circuit Rail-to-Rail SC-70-5; Manufacturer: Texas Instruments; Gain Bandwidth: 1MHz; AEC Qualified: No; Min Dual Supply Voltage: 850mV; TaMax_C: +125°C; Voltage Gain: 121dB; Nominal Supply Current: 24uA; Max Dual Supply Voltage: 2.75V; Number Of Channels: 1; Max Supply Voltage: 5.5V; Output Current Per Channel: 60mA; Standoff Height: 0mm; Response Time: 8us; TaMin_C: -40°C; SizeZ_mm: 1.1mm; Input Offset Voltage: 0.06mV; Min Supply Voltage: 1.7V; Input Bias Current: 0.00000001uA
U6 = CMP-0081715-3: 33 V Bidirectional Flat-Clamp Surge Protection Device, DRB0008A (VSON-8); Alternate PartNumber: TVS3301DRBT; Alternate Manufacturer: Texas Instruments; SizeZ_mm: 1.0; SizeX_mm: 3.0; AEC Category: Q200; SizeAreaWB_mm2: 16.0; CompType: IC; Rating: Catalog; SizeArea_mm2: 9.0; AEC Qualified: N
U7 = CMP-0123563-1: 1.65-V to 5.5-V 8-bit parallel-load shift register with voltage translation; Manufacturer: Texas Instruments; SizeZ_mm: 0.8mm; AEC Qualified: No; Frequency_Fixed: 37.7MHz; Max Supply Voltage: 5.5V; Min Supply Voltage: 1.65V; Nominal Supply Current: 2uA; Number Of Inputs: 8; Number Of Outputs: 2; PositionCount: 1; Standoff Height: 0mm; TaMax_C: +125°C; TaMin_C: -40°C
U8 = CMP-0860319-1: 1-ch, 2:1 general-purpose analog multiplexer with 1.8-V logic control, DCK0006A (SOT-SC70-6); Alternate Manufacturer: Texas Instruments; SizeY_mm: 2; SizeArea_mm2: 4.2; SizeX_mm: 2.1; AEC Category: Q200; Rating: Catalog; CompType: IC; SizeZ_mm: 1.1; SizeAreaWB_mm2: 9.3; AEC Qualified: N

## Sheet AFE882H1-FE_Hardware.SchDoc
size 431 x 279 mm; Date: Not shown in title block; ApprovedBy: Not shown in title block; CheckedBy: Not shown in title block; Author: Not shown in title block; CompanyName: Not shown in title block; Engineer: Not shown in title block; Organization: Not shown in title block; Address1: Not shown in title block; Address2: Not shown in title block; Address3: Not shown in title block; Address4: Not shown in title block; DocumentNumber: 3; Revision: Use project parameter SCH_Rev; SheetNumber: 3; SheetTotal: 3; PageSetup: Record=PageOptions¦CenterHorizontal=True¦CenterVertical=True¦PrintScale=1.00¦XCorrection=1.00¦YCorrection=1.00¦PrintKind=0¦BorderSize=5000000¦LeftOffset=0¦BottomOffset=0¦Orientation=2¦PaperLength=1000¦PaperWidth=1000¦Scale=100¦PaperSource=15¦PrintQuality=600¦MediaType=1¦DitherType=10¦PaperKind=Letter¦PrintScaleMode=1
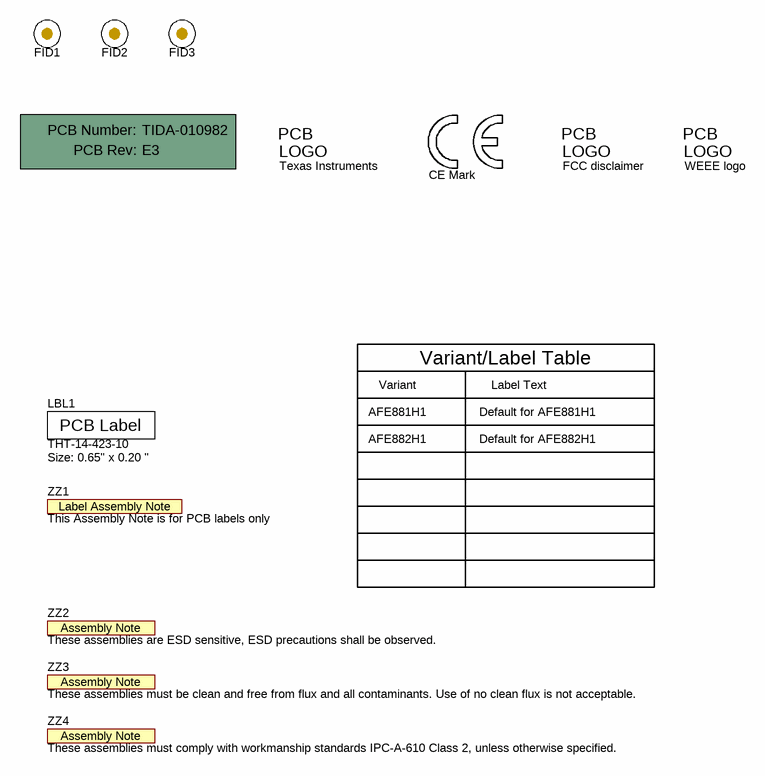
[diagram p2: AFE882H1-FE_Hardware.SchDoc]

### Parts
!PCB1  Printed Circuit Board  (value not drawn)  (mechanical)
FID1  Fiducial  [Fiducial10-20]  (value not drawn)
FID2  Fiducial  [Fiducial10-20]  (value not drawn)
FID3  Fiducial  [Fiducial10-20]  (value not drawn)
LBL1  THT-14-423-10  Note: Size: 0.65" x 0.20 "  [Label_650x200]
Logo1  CE Mark  [CE_Mark_5mm]  (no BOM)
Logo2  Texas Instruments  [TI_Symbol_Overlay_Small]  (no BOM)
Logo3  FCC disclaimer  [FCC_disclaimer]  (no BOM)
Logo4  WEEE logo  [WEEE_Minimum]  (no BOM)
ZZ1  This Assembly Note is for PCB labels only  [AssemblyNoteLabel]  (no BOM)
ZZ2  These assemblies are ESD sensitive, ESD precautions shall be observed.  [AssemblyNote]  (no BOM)
ZZ3  These assemblies must be clean and free from flux and all contaminants. Use of no clean flux is not acceptable.  [AssemblyNote]  (no BOM)
ZZ4  These assemblies must comply with workmanship standards IPC-A-610 Class 2, unless otherwise specified.  [AssemblyNote]  (no BOM)

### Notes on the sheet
- Variant
- Variant/Label Table
- Label Text
- AFE881H1
- AFE882H1
- Default for AFE881H1
- Default for AFE882H1

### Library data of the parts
!PCB1 = CMP-0003618-2: Manufacturer: Any; PartNumber: TIDA-010982
FID1-FID3 = CMP-0077181-1: Fiducial mark.  There is nothing to buy or mount.
LBL1 = CMP-0003625-1: Thermal Transfer Printable Labels, 0.650" W x 0.200" H - 10,000 per roll; Manufacturer: Brady; CompType: Label
Logo1 = CMP-0074844-1: SymbolCreator: a0412235
Logo2 = CMP-0074838-1: Texas Instrument Corporate Signature; SymbolCreator: a0412235; Lib Reference: TI_Logo; Library Reference: Logo
Logo3 = CMP-0074847-1: FCC_disclaimer; Library Reference: Logo
Logo4 = CMP-0074769-1
ZZ1 = CMP-0003616-3
ZZ2 = CMP-0077236-1
ZZ3 = CMP-0077237-1
ZZ4 = CMP-0077238-1

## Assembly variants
AFE881H1: not fitted D3 D5 D6 D7 FID1 FID2 FID3 R5 R8 R10 R12 R15; alternate parts R9 -> CMP-0024852-2, U4 -> CMP-0092434-1, R6 -> CMP-0023413-3, R7 -> CMP-0024512-3, R4 -> CMP-0023098-5, R14 -> CMP-0023541-3, C15 -> CMP-0064933-4, R13 -> CMP-0020058-2, R23 -> CMP-0020058-2
AFE882H1: not fitted D3 D5 D6 D7 J5 J8 Q6 R8 R10 R12 R15 R16 R23 SH-J3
